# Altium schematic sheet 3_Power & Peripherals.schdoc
size 309 x 223 mm; Symbol: Artery_A4; Device: Artery_A4; Company: Artery Technology; Drawed: SD; Version: 1.0; Page Size: A4; @Project Name: AT-START-F455; @Page Count: 4; @Update Date: 2025-01-22; @Create Date: 2024-11-06; @Schematic Name: AT-START-F455 V1.0; @Page No: 3; @Page Name: Power & Peripherals; @Board Name: AT-START-F455_v1.0; @Create Time: 09:01:18; @Update Time: 18:15:52
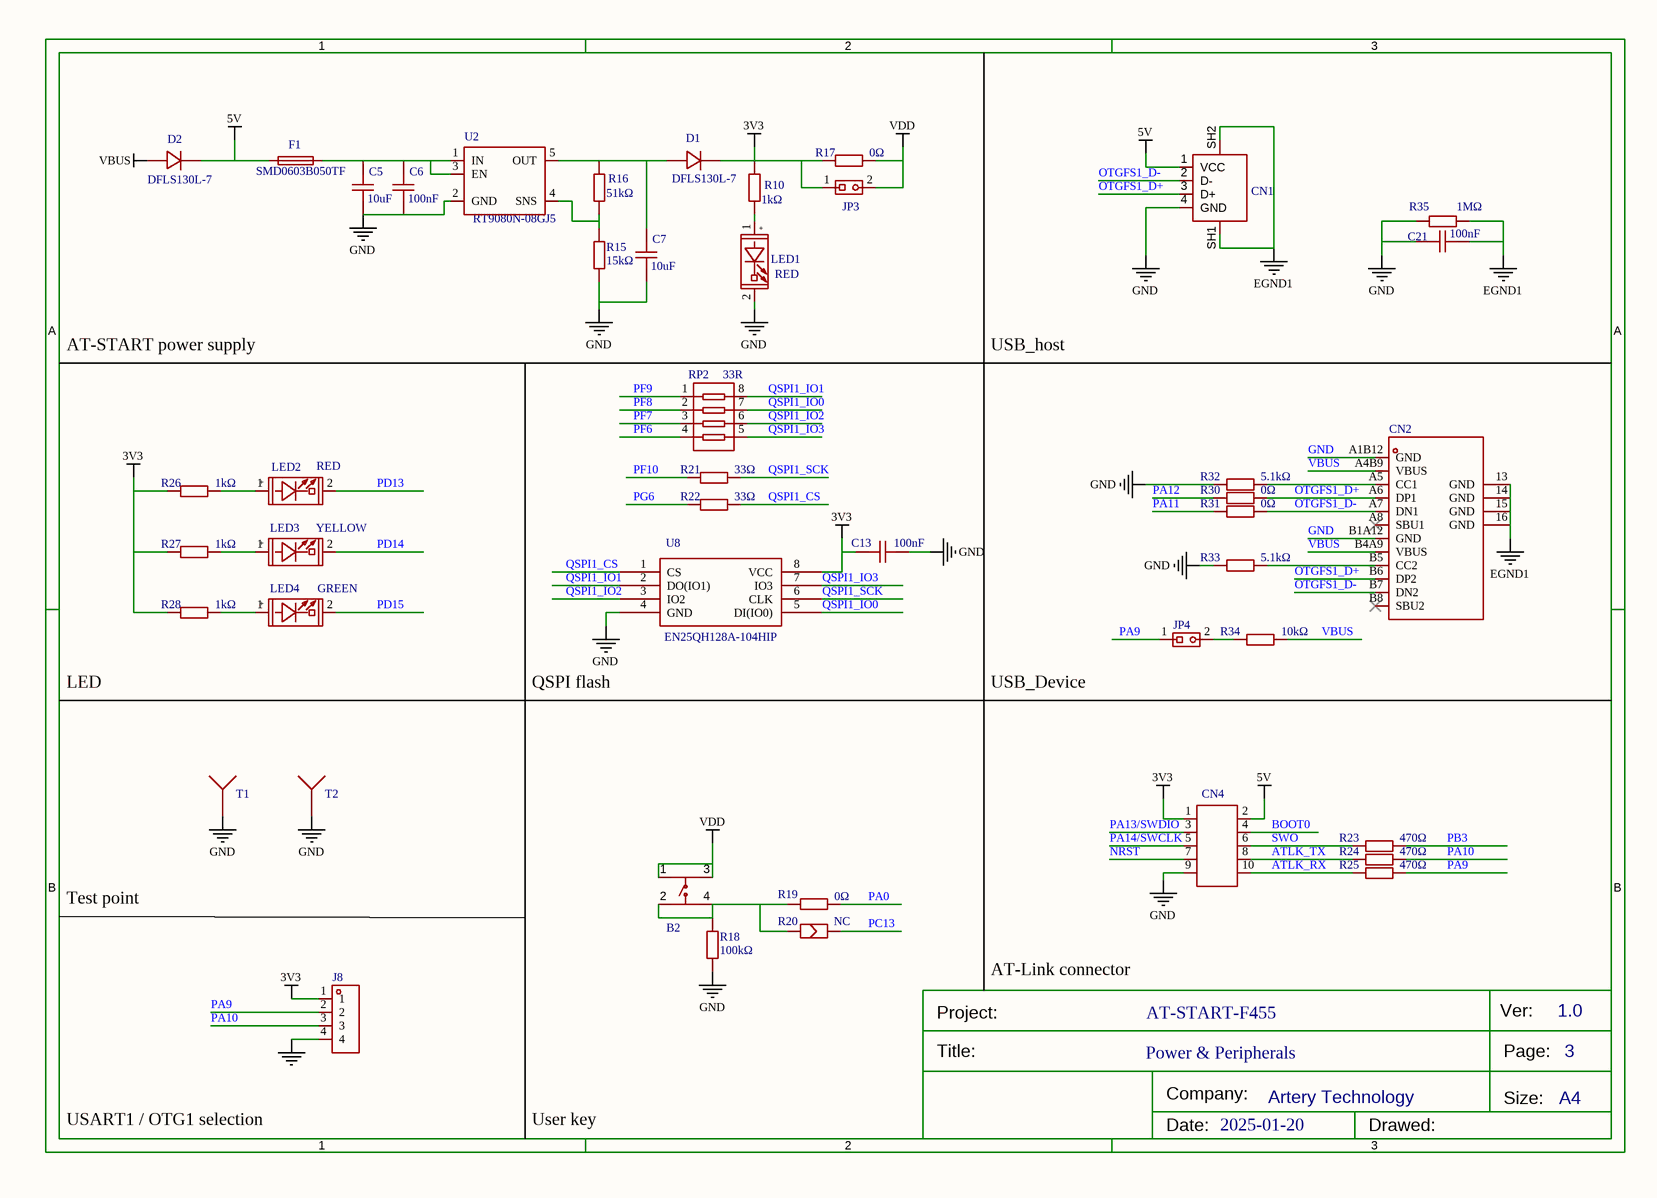
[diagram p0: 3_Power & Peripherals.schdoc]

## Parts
B2  贴片按键6*6*5 红色  [SW-SMD_4P-L6.0-W6.0-P4.50-LS9.0]  (value not drawn)
C5  10uF  [C0603]
C6  100nF  [C0603]
C7  10uF  [C0603]
C13  100nF  [C0603]
C21  100nF  [C0603]
CN1  JTJ-USB-AF-08  [USB-A-TH__USB-AF-90]  (value not drawn)
CN2  (no value)  [USB-C-SMD_TYPEC-304-BCP16]
CN4  CON10A_0  [HDR2X5]  (value not drawn)
D1  DFLS130L-7  [POWERDI-123_L2.8-W1.8-LS3.7-RD]
D2  DFLS130L-7  [POWERDI-123_L2.8-W1.8-LS3.7-RD]
F1  SMD0603B050TF  [R0603]
J8  PZ2.54-1*4-WZ  [HDR-TH_4P-P2.54-H-M-W7.7-P]  (value not drawn)
JP3  Jumper 1x2P  [HEADER 1X2]  (value not drawn)
JP4  Jumper 1x2P  [HEADER 1X2]  (value not drawn)
LED1  RED  [LED0603]
LED2  RED  [LED0603]
LED3  YELLOW  [LED0603]
LED4  GREEN  [LED0603]
R10  1kΩ  [R0603]
R15  15kΩ  [R0603]
R16  51kΩ  [R0603]
R17  0Ω  [R0603]
R18  100kΩ  [R0603]
R19  0Ω  [R0603]
R20  NC  [SB-PAD]
R21  33Ω  [R0603]
R22  33Ω  [R0603]
R23  470Ω  [R0603]
R24  470Ω  [R0603]
R25  470Ω  [R0603]
R26  1kΩ  [R0603]
R27  1kΩ  [R0603]
R28  1kΩ  [R0603]
R30  0Ω  [R0603]
R31  0Ω  [R0603]
R32  value 5.1kΩ  [R0603]
R33  value 5.1kΩ  [R0603]
R34  10kΩ  [R0603]
R35  value 1MΩ  [R0603]
RP2  33R  [0603*4,8P4R]
T1  TESTPOINT TP-5006  [TESTHOOK]  (value not drawn)
T2  TESTPOINT TP-5006  [TESTHOOK]  (value not drawn)
U2  RT9080N-08GJ5  [SOT-23-5]
U8  EN25QH128A-104HIP  [SOIC-8_208MIL]

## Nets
3V3: C13.1 CN4.1 D1.1 J8.1 JP3.1 R10.1 R17.1 R26.1 R27.1 R28.1 U8.8(VCC)
5V: CN1.1(VCC) CN4.2 D2.1 F1.1
EGND1: C21.1 CN1.SH1 CN1.SH2 CN2.13(GND) CN2.14(GND) CN2.15(GND) CN2.16(GND) R35.2
GND: C5.2 C6.2 C7.2 C13.2 C21.2 CN1.4(GND) CN2.A1B12(GND) CN2.B1A12(GND) CN4.9 J8.4 LED1.2(CATHODE) R15.2 R18.1 R32.1 R33.1 R35.1 T1.1 T2.1 U2.2(GND) U8.4(GND)
VBUS: CN2.A4B9(VBUS) CN2.B4A9(VBUS) D2.2 R34.2
VDD: B2.1 B2.3 JP3.2 R17.2
ATLK_RX: CN4.10 R25.1
ATLK_TX: CN4.8 R24.1
BOOT0: CN4.4
NRST: CN4.7
OTGFS1_D+: CN1.3(D+) CN2.A6(DP1) CN2.B6(DP2) R30.2
OTGFS1_D-: CN1.2(D-) CN2.A7(DN1) CN2.B7(DN2) R31.2
PA0: R19.2
PA9: J8.2 JP4.1 R25.2
PA10: J8.3 R24.2
PA11: R31.1
PA12: R30.1
PA13/SWDIO: CN4.3
PA14/SWCLK: CN4.5
PB3: R23.2
PC13: R20.2
PD13: LED2.2(CATHODE)
PD14: LED3.2(CATHODE)
PD15: LED4.2(CATHODE)
PF6: RP2.4
PF7: RP2.3
PF8: RP2.2
PF9: RP2.1
PF10: R21.1
PG6: R22.1
QSPI1_CS: R22.2 U8.1(CS)
QSPI1_IO0: RP2.7 U8.5(DI(IO0))
QSPI1_IO1: RP2.8 U8.2(DO(IO1))
QSPI1_IO2: RP2.6 U8.3(IO2)
QSPI1_IO3: RP2.5 U8.7(IO3)
QSPI1_SCK: R21.2 U8.6(CLK)
SWO: CN4.6 R23.1
NetB2_2: B2.2 B2.4 R18.2 R19.1 R20.1
NetC5_1: C5.1 C6.1 F1.2 U2.1(IN) U2.3(EN)
NetC7_1: C7.1 D1.2 R16.2 U2.5(OUT)
NetCN2_A5: CN2.A5(CC1) R32.2
NetCN2_B5: CN2.B5(CC2) R33.2
NetJP4_2: JP4.2 R34.1
NetLED1_1: LED1.1(ANODE) R10.2
NetLED2_1: LED2.1(ANODE) R26.2
NetLED3_1: LED3.1(ANODE) R27.2
NetLED4_1: LED4.1(ANODE) R28.2
NetR15_1: R15.1 R16.1 U2.4(SNS)

Not connected (* = marked no-connect by the designer): CN2 A8(SBU1)* B8(SBU2)*

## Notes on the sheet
- AT-START power supply
- USB_host
- LED
- QSPI flash
- USB_Device
- Test point
- AT-Link connector
- AT-START-F455
- USART1 / OTG1 selection
- User key
- 2025-01-20

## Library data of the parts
B2 = K2-1102SP-C3SC-04: Manufacturer: Korean Hroparts Elec; Symbol: 贴片按键6*6*5 黑色; Paste Type: expand; Convert to PCB: yes
C5 C7 = CL10A106KP8NNNC: Manufacturer: SAMSUNG(三星); Add into BOM: yes; Tolerance: ±10%; Voltage Rated: 10V; Temperature Coefficient: X5R; Origin Footprint: 0603_C-M
C6 C13 = CC0603KRX7R9BB104: Manufacturer: YAGEO(国巨); Add into BOM: yes; Tolerance: ±10%; Voltage Rated: 50V; Temperature Coefficient: X7R; Origin Footprint: 0603_C-M
C21 = CC0603KRX7R9BB104: Manufacturer: YAGEO(国巨); Add into BOM: yes; Tolerance: ±10%; Voltage Rated: 50V; Temperature Coefficient: X7R
CN1 = JTJ-USB-AF-08: Paste Type: expand; Convert to PCB: yes
CN2 = TYPEC-304-BCP16: Manufacturer: XUNPU(讯普); Add into BOM: yes; Connector Type: Type-C; Gender: 母座; Number of Contacts: 16.0; Number of Ports: 1; Mounting Sytle: 卧贴; Current Rating - Power (Max): 3A; Welding Temperature (Max): 260
CN4 = CON10A_0: Convert to PCB: yes
D1 D2 = DFLS130L-7: Manufacturer: Diodes Incorporated; Paste Type: expand; Convert to PCB: yes
F1 = SMD0603B035TF: Manufacturer: Brightking Elec (TAIWAN); Paste Type: expand; Convert to PCB: yes
J8 = PZ2.54-1*4-WZ: Manufacturer: ZHOURI(洲日); Add into BOM: yes; Pin Structure: 1x4P; Pitch: 2.54mm; Origin Footprint: HDR1X4
JP3 JP4 = Jumper 1x2P: Convert to PCB: yes
LED1 LED2 = RED: Convert to PCB: yes
LED3 = YELLOW: Convert to PCB: yes
LED4 = GREEN: Convert to PCB: yes
R10 R26-R28 = 0603WAF1001T5E: Manufacturer: UNI-ROYAL(厚声); Add into BOM: yes; Tolerance: ±1%; Power(Watts): 100mW; Temperature Coefficient: ±100ppm/℃; Overload Voltage (Max): 75V
R15 = 0603WAF1502T5E: Manufacturer: UNI-ROYAL(厚声); Add into BOM: yes; Tolerance: ±1%; Power(Watts): 100mW; Temperature Coefficient: ±100ppm/℃; Overload Voltage (Max): 75V
R16 = 0603WAF5102T5E: Manufacturer: UNI-ROYAL(厚声); Add into BOM: yes; Tolerance: ±1%; Power(Watts): 100mW; Temperature Coefficient: ±100ppm/℃; Overload Voltage (Max): 75V
R17 R19 = 0603WAF0000T5E: Manufacturer: UNI-ROYAL(厚声); Add into BOM: yes; Tolerance: ±1%; Power(Watts): 100mW; Overload Voltage (Max): 75V
R18 = 0603WAF1003T5E: Manufacturer: UNI-ROYAL(厚声); Add into BOM: yes; Tolerance: ±1%; Power(Watts): 100mW; Temperature Coefficient: ±100ppm/℃; Overload Voltage (Max): 75V
R20 = NC: Convert to PCB: yes
R21 R22 = 0603WAF330JT5E: Manufacturer: UNI-ROYAL(厚声); Add into BOM: yes; Tolerance: ±1%; Power(Watts): 100mW; Temperature Coefficient: ±100ppm/℃; Overload Voltage (Max): 75V
R23-R25 = 0603WAF4700T5E: Manufacturer: UNI-ROYAL(厚声); Add into BOM: yes; Tolerance: ±1%; Power(Watts): 100mW; Temperature Coefficient: ±100ppm/℃; Overload Voltage (Max): 75V
R30 R31 = 0603WAF0000T5E: Manufacturer: UNI-ROYAL(厚声); Add into BOM: yes; Tolerance: ±1%; Power(Watts): 100mW; Overload Voltage (Max): 75V; Temperature Coefficient: ±100ppm/℃
R32 R33 = 0603WAF5101T5E: Manufacturer: UNI-ROYAL(厚声); Add into BOM: yes; Tolerance: ±1%; Power(Watts): 1/10W; Temperature Coefficient: ±100ppm/; Overload Voltage (Max): 75V
R34 = 0603WAF1002T5E: Manufacturer: UNI-ROYAL(厚声); Add into BOM: yes; Tolerance: ±1%; Power(Watts): 100mW; Temperature Coefficient: ±100ppm/℃; Overload Voltage (Max): 75V
R35 = RC0603FR-071ML: Manufacturer: YAGEO(国巨); Add into BOM: yes; Tolerance: ±1%; Power(Watts): 100mW; Temperature Coefficient: ±100ppm/; Overload Voltage (Max): 75V
RP2 = 33R: Convert to PCB: yes
T1 T2 = TESTPOINT TP-5006: Convert to PCB: yes
U2 = RT9080N-08GJ5: Convert to PCB: yes
U8 = EN25QH128A-104HIP: Convert to PCB: yes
